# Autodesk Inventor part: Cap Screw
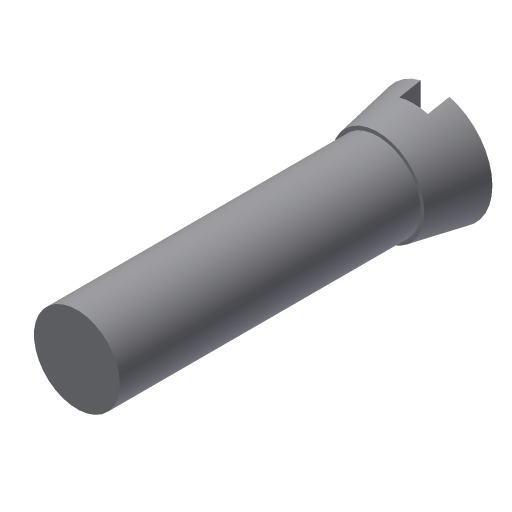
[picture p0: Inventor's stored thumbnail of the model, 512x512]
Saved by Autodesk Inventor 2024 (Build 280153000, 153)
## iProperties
Shininess: 77.0
Length Units: 11269
Angle Units: 11279
Time Units: 11290
Mass Units: 11283
Length Display Precision: 3
Angle Display Precision: 2
Created: 2002-02
Part Number: Cap Screw
Document SubType Name: Modeling
Designer: ***
Density: 1 g/cm^3
Material: Generic
Appearance: Default
Density: 0.0
Volumn: 0.0
Area: 0.0
PropertySet Name: Model Information
Control State: 0
Master: False
Checked Out: False
Author: ***
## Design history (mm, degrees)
sketch "Sketch1"
  geometry: L1 (0, 27.83)-(4, 27.83); L2 (4, 27.83)-(3.25, 23.83); L3 (3.25, 23.83)-(0, 23.83); L4 (0, 23.83)-(0, 27.83)
  constraints: 8 end point, 1 horizontal, 1 parallel, 1 perpendicular, 1 point on line
  dimensions: "d2" = 4 distance from line of L1 L2.end; "d5" = 8 diameter of L1.end L4; "d6" = 6.5 diameter of L3.start L4; "d14" = 4 distance of L3.end L1.start
revolve "Revolution1" sketch "Sketch1" stored, may be unused: angle "d7" = 90 deg
sketch "Sketch2"
  geometry: C1 r 3 at (0, 0)
  constraints: 1 centre point
  dimensions: "d8" = 6 diameter of C1
extrude "Extrusion1" join sketch "Sketch2" distance "d9" = 21; taper "d10" = 0 deg
sketch "Sketch3"
  geometry: L1 (-1, 28.967)-(1, 28.967); L2 (1, 28.967)-(1, 26.33); L3 (1, 26.33)-(-1, 26.33); L4 (-1, 26.33)-(-1, 28.967); L5 (-4, 27.83)-(4, 27.83) reference
  constraints: 8 end point, 2 parallel, 1 horizontal, 1 perpendicular
  dimensions: "d11" = 2 distance of L1.start L1.end; "d15" = 1.5 distance between parallel lines of L5 L3
extrude "Extrusion2" cut sketch "Sketch3" extent not by distance; stored distance "d12" = 24; taper "d13" = 0 deg
body "Solid1"
